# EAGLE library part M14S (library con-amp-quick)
AMP QUICK CONNECTOR
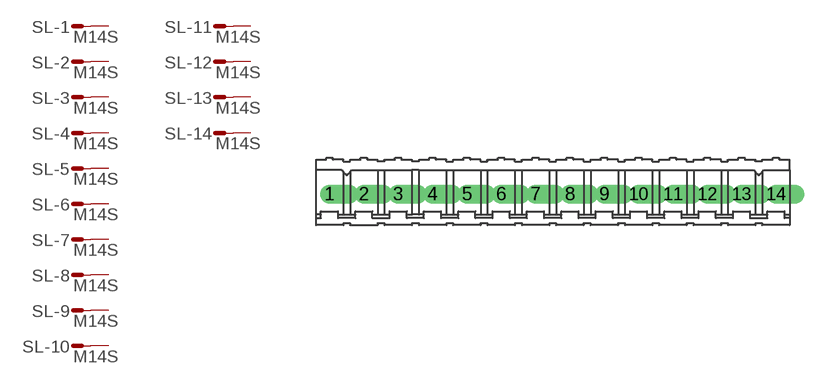
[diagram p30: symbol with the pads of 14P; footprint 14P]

Designator prefix SL; gates -1=M -2=M -3=M -4=M -5=M -6=M -7=M -8=M -9=M -10=M -11=M -12=M -13=M -14=M

## M14S  [14P]
1  -1:S  pas
2  -2:S  pas
3  -3:S  pas
4  -4:S  pas
5  -5:S  pas
6  -6:S  pas
7  -7:S  pas
8  -8:S  pas
9  -9:S  pas
10  -10:S  pas
11  -11:S  pas
12  -12:S  pas
13  -13:S  pas
14  -14:S  pas

## Footprint 14P (pad centres in mm)
AMP QUICK CONNECTOR
drill 0.914 offset: 1 -16.51,0; 2 -13.97,0; 3 -11.43,0; 4 -8.89,0; 5 -6.35,0; 6 -3.81,0; 7 -1.27,0; 8 1.27,0; 9 3.81,0; 10 6.35,0; 11 8.89,0; 12 11.43,0; 13 13.97,0; 14 16.51,0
